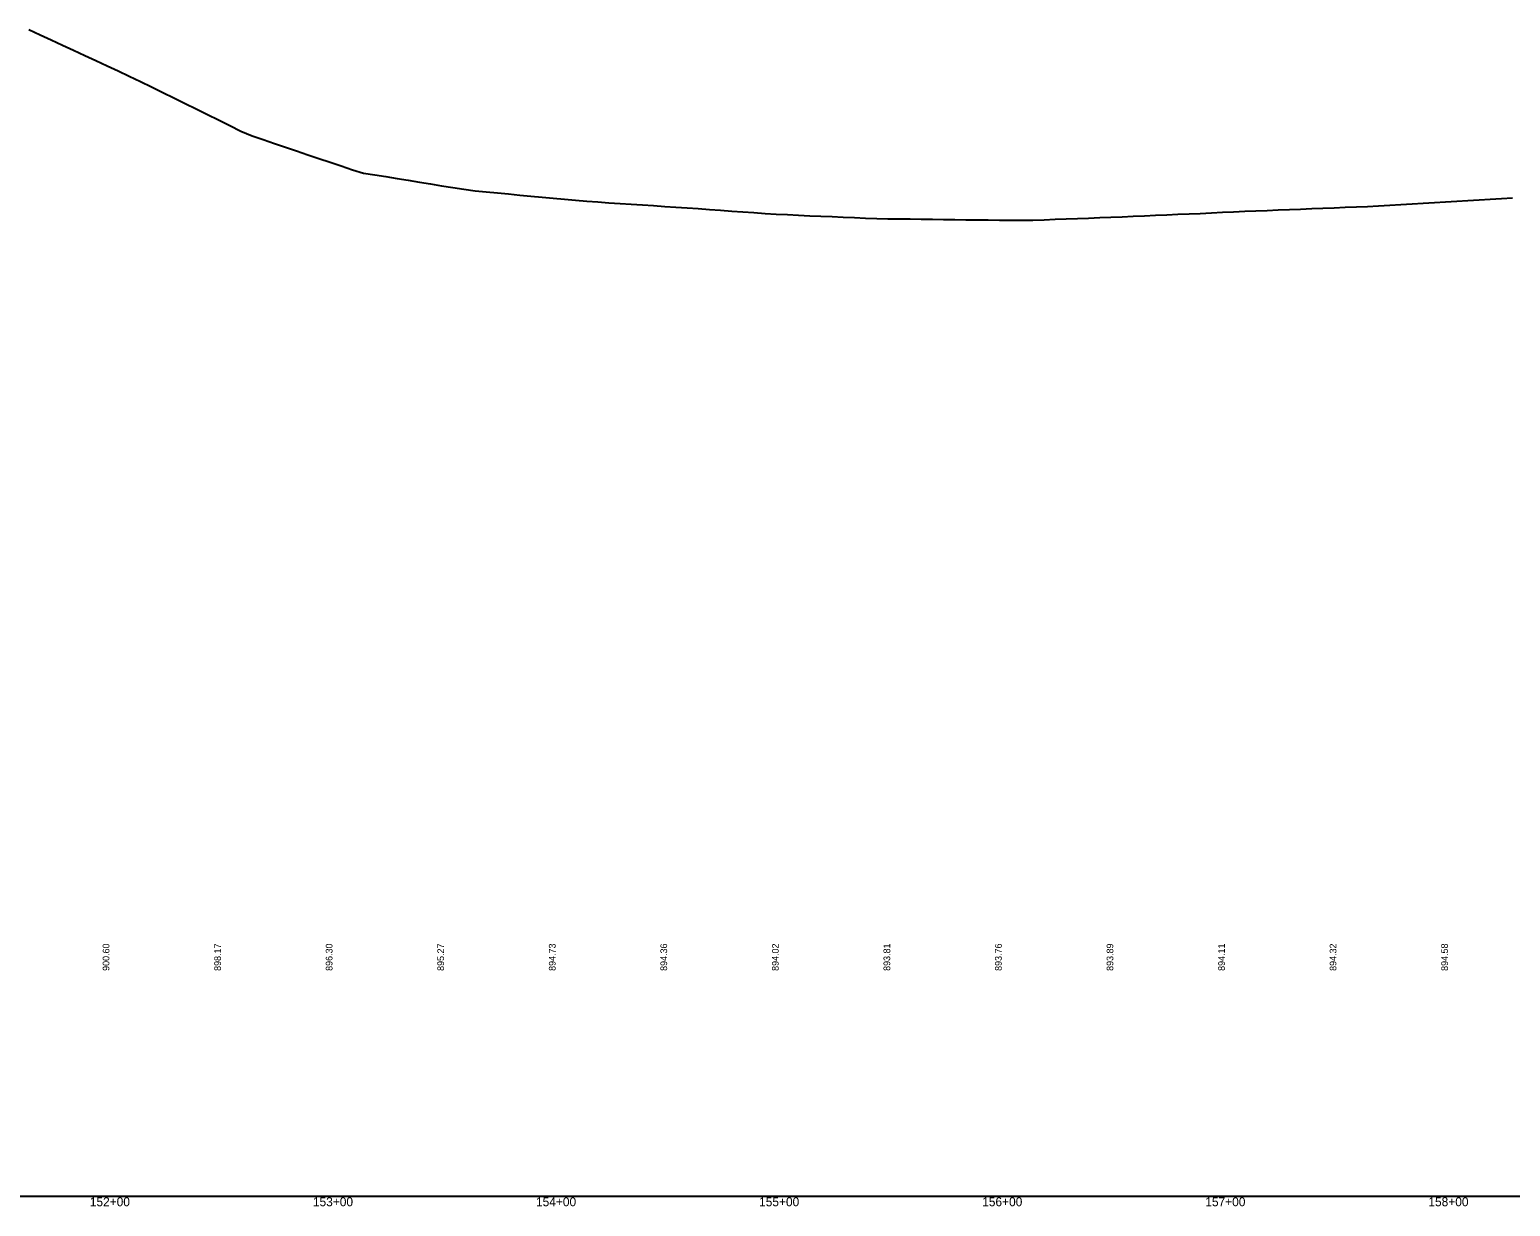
# Model space of a CAD drawing. Extents: x 1475774 to 1484571, y 1098511 to 1113011.
# Drawn here: x 1478235 to 1478898, y 1110507 to 1111034 of the extents above; entities that cross this region are included whole.
import ezdxf

# ---------------------------------------------------------------- set-up
doc = ezdxf.new("R2010")
doc.units = 0
for name, color, linetype in [('RD_DDB_Profile_EX', 7, 'Continuous'), ('RD_DDB_StaTX', 7, 'Continuous'), ('RD_DDB_StripGrade', 7, 'Continuous'), ('RD_GPK_Profile_Cell', 7, 'Continuous')]:
    doc.layers.add(name, color=color, linetype=linetype)

msp = doc.modelspace()

# ---------------------------------------------------------------- linework, layer by layer
at = {"layer": 'RD_DDB_Profile_EX'}
for points in [[(1478234.42, 1111034.17), (1478239.42, 1111031.86), (1478244.42, 1111029.54), (1478249.42, 1111027.23), (1478254.42, 1111024.92), (1478259.42, 1111022.6), (1478264.42, 1111020.29), (1478269.42, 1111017.97), (1478274.42, 1111015.66), (1478279.42, 1111013.34), (1478284.42, 1111010.98), (1478289.42, 1111008.51), (1478294.42, 1111006.03), (1478299.42, 1111003.56), (1478304.42, 1111001.08), (1478309.42, 1110998.62), (1478314.42, 1110996.15), (1478319.42, 1110993.67), (1478324.42, 1110991.2), (1478329.42, 1110988.72), (1478334.42, 1110986.54), (1478339.42, 1110984.86), (1478344.42, 1110983.17), (1478349.42, 1110981.49), (1478354.42, 1110979.8), (1478359.42, 1110978.1), (1478364.42, 1110976.42), (1478369.42, 1110974.73), (1478374.42, 1110973.05), (1478379.42, 1110971.37), (1478384.42, 1110969.88), (1478389.42, 1110969.07), (1478394.42, 1110968.26), (1478399.42, 1110967.44), (1478404.42, 1110966.63), (1478409.42, 1110965.83), (1478414.42, 1110965.02), (1478419.42, 1110964.21), (1478424.42, 1110963.39), (1478429.42, 1110962.58), (1478434.42, 1110961.87), (1478439.42, 1110961.41), (1478444.42, 1110960.95), (1478449.42, 1110960.49), (1478454.42, 1110960.03), (1478459.42, 1110959.58), (1478464.42, 1110959.12)], [(1478464.42, 1110959.12), (1478469.42, 1110958.66), (1478474.42, 1110958.2), (1478479.42, 1110957.73), (1478484.42, 1110957.27), (1478489.42, 1110956.93), (1478494.42, 1110956.6), (1478499.42, 1110956.27), (1478504.42, 1110955.94), (1478509.42, 1110955.6), (1478514.42, 1110955.26), (1478519.42, 1110954.93), (1478524.42, 1110954.59), (1478529.42, 1110954.26), (1478534.42, 1110953.94), (1478539.42, 1110953.58), (1478544.42, 1110953.22), (1478549.42, 1110952.86), (1478554.42, 1110952.5), (1478559.42, 1110952.16), (1478564.42, 1110951.8), (1478569.42, 1110951.47), (1478574.42, 1110951.23), (1478579.42, 1110950.99), (1478584.42, 1110950.75), (1478589.42, 1110950.51), (1478594.42, 1110950.38), (1478599.42, 1110950.14), (1478604.42, 1110949.91), (1478609.42, 1110949.67), (1478614.42, 1110949.44), (1478619.42, 1110949.39), (1478624.42, 1110949.35), (1478629.42, 1110949.31), (1478634.42, 1110949.27), (1478639.42, 1110949.23), (1478644.42, 1110949.03), (1478649.42, 1110949), (1478654.42, 1110948.96), (1478659.42, 1110948.92), (1478664.42, 1110948.89), (1478669.42, 1110948.83), (1478674.42, 1110948.79), (1478679.42, 1110948.75), (1478684.42, 1110948.76), (1478689.42, 1110948.96), (1478694.42, 1110949.15), (1478699.42, 1110949.34), (1478704.42, 1110949.54), (1478709.42, 1110949.72), (1478714.42, 1110949.91), (1478719.42, 1110950.11), (1478724.42, 1110950.31), (1478729.42, 1110950.5), (1478734.42, 1110950.7), (1478739.42, 1110950.93), (1478744.42, 1110951.15), (1478749.42, 1110951.38), (1478754.42, 1110951.6), (1478759.42, 1110951.82), (1478764.42, 1110952.05), (1478769.42, 1110952.27), (1478774.42, 1110952.5), (1478779.42, 1110952.72), (1478784.42, 1110952.95), (1478789.42, 1110953.15), (1478794.42, 1110953.36), (1478799.42, 1110953.56), (1478804.42, 1110953.76), (1478809.42, 1110953.95), (1478814.42, 1110954.15), (1478819.42, 1110954.34), (1478824.42, 1110954.53), (1478829.42, 1110954.73), (1478834.42, 1110954.92), (1478839.42, 1110955.18), (1478844.42, 1110955.47), (1478849.42, 1110955.76), (1478854.42, 1110956.05), (1478859.42, 1110956.34), (1478864.42, 1110956.64), (1478869.42, 1110956.93), (1478874.42, 1110957.22), (1478879.42, 1110957.51), (1478884.42, 1110957.81), (1478889.42, 1110958.12), (1478894.42, 1110958.44), (1478899.42, 1110958.76)]]:
    msp.add_lwpolyline(points, dxfattribs=at)
at = {"layer": 'RD_GPK_Profile_Cell'}
msp.add_line((1477570.98, 1110511.25), (1484570.98, 1110511.25), dxfattribs=at)

# ---------------------------------------------------------------- texts
at = {"layer": 'RD_DDB_StaTX'}
for s, p in [('152+00', (1478261.7, 1110506.75)), ('153+00', (1478361.7, 1110506.75)), ('154+00', (1478461.7, 1110506.75)), ('155+00', (1478561.7, 1110506.75)), ('156+00', (1478661.7, 1110506.75)), ('157+00', (1478761.7, 1110506.75)), ('158+00', (1478861.7, 1110506.75))]:
    msp.add_text(s, height=4, dxfattribs=at).set_placement(p)
at = {"layer": 'RD_DDB_StripGrade'}
for s, p in [('900.60', (1478270.48, 1110612.25)), ('898.17', (1478320.48, 1110612.25)), ('896.30', (1478370.48, 1110612.25)), ('895.27', (1478420.48, 1110612.25)), ('894.73', (1478470.48, 1110612.25)), ('894.36', (1478520.48, 1110612.25)), ('894.02', (1478570.48, 1110612.25)), ('893.81', (1478620.48, 1110612.25)), ('893.76', (1478670.48, 1110612.25)), ('893.89', (1478720.48, 1110612.25)), ('894.11', (1478770.48, 1110612.25)), ('894.32', (1478820.48, 1110612.25)), ('894.58', (1478870.48, 1110612.25))]:
    msp.add_text(s, height=3, rotation=90, dxfattribs=at).set_placement(p)

doc.saveas('drawing.dxf')
